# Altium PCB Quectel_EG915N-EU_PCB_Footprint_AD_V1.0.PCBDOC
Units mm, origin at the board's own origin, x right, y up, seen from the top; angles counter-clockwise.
Board outline 152.4 x 101.6 mm, 2 copper layers (Top Layer, Bottom Layer); 1 components, 0 nets, 126 pads, 0 vias.
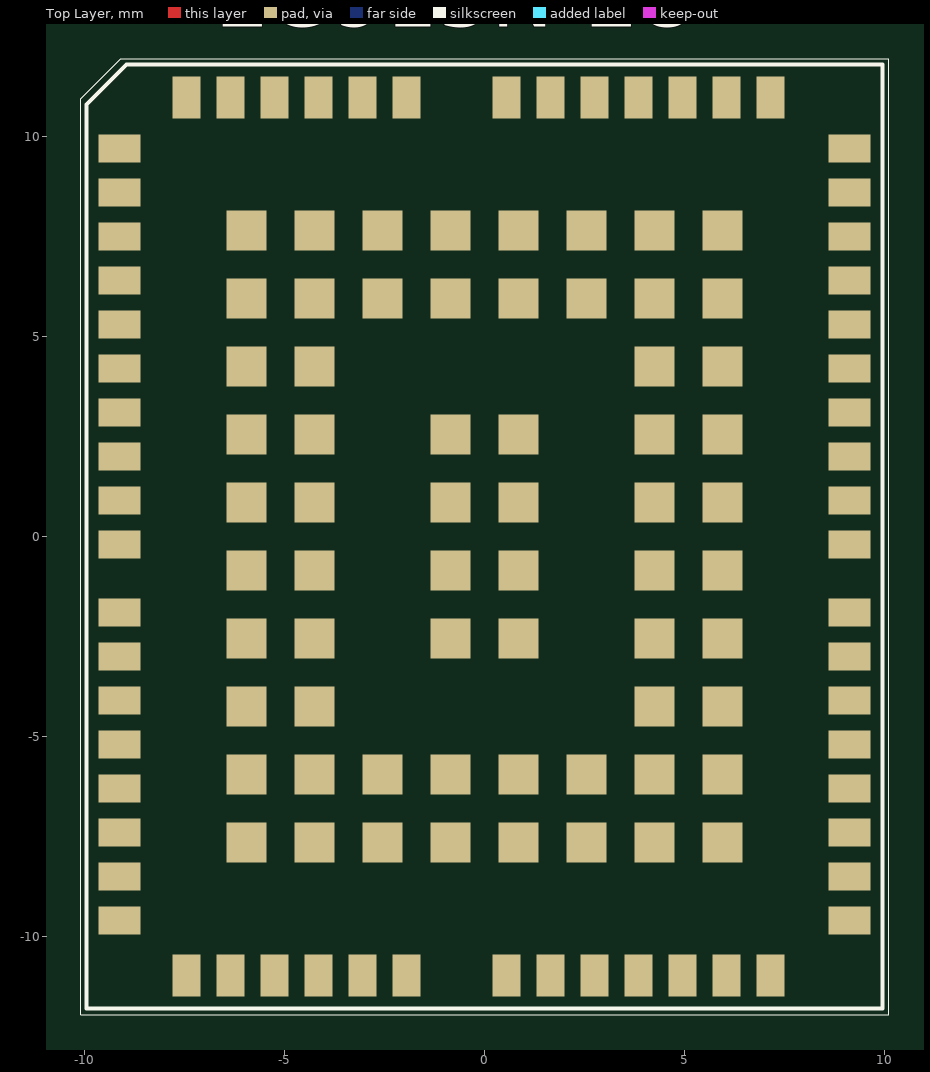
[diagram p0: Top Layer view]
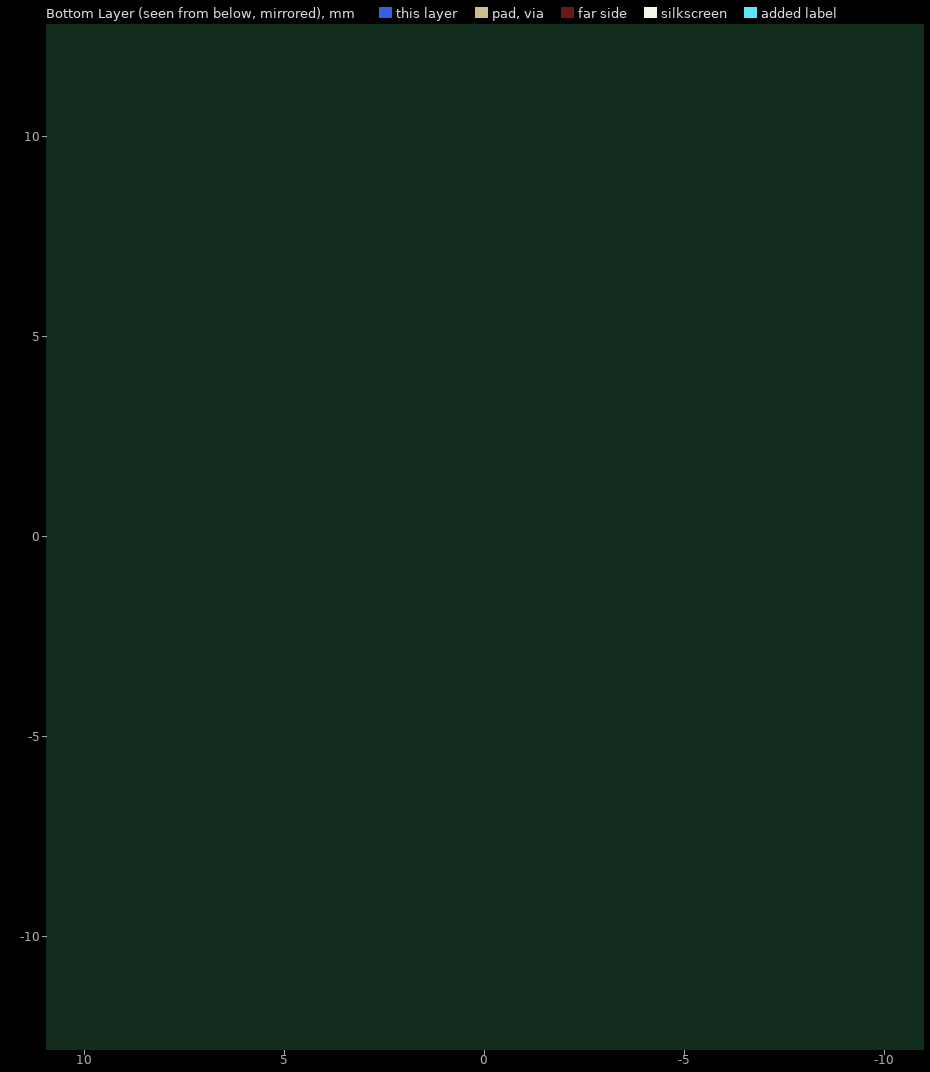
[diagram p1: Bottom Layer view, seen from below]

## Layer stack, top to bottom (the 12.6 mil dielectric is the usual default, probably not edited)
Top Layer: signal copper 0.0356
Dielectric: dielectric 0.32, FR-4, Dk 4.8
Bottom Layer: signal copper 0.0356

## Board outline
-50.546,-45.466 101.854,-45.466 101.854,56.134 -50.546,56.134

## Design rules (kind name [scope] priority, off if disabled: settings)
Clearance [All] p1: gap=0.254
FabricationTestPointUsage TestPointUsage [All] p1: valid=0 allowmultiple=FALSE
FabricationTestpoint Testpoint [(IsPad And (OnTopLayer Or OnBottomLayer))] p1: side=3 testpointundercomponent=TRUE minsize=1.016 maxsize=2.54 preferedsize=1.524 minholesize=0 maxholesize=1.016 preferedholesize=0.813 testpointgrid=0.025 allowsidetop=TRUE allowsidebottom=TRUE usegrid=TRUE gridtolerance=0
PolygonConnect [All] p1: connectstyle=Relief reliefconductorwidth=0.254 reliefentries=4 polygonreliefangle="90 Angle" airgapwidth=0.254
RoutingVias [All] p1: holewidth=0.711 width=1.27 viastyle="Through Hole" minholewidth=0.711 minwidth=1.27 maxholewidth=0.711 maxwidth=1.27
SolderMaskExpansion [All] p1: expansion=0.102
Width [All] p1: maxlimit=0.254 minlimit=0.254 preferedwidth=0.254
26 further rules are at their usual default settings.

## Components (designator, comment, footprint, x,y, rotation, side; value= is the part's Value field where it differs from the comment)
EG915N-EU "Comment" EG915N-EU 0,0 r0 top

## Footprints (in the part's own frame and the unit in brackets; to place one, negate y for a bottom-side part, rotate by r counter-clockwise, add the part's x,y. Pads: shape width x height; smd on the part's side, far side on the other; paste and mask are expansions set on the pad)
EG915N-EU [mm] "EG915U  Module LGA126Pin  19.9x23.6mm H2.4mm RO"
  rect 1.05x0.7 smd mask+0.05: 1(-9.125,9.7) 2(-9.125,8.6) 3(-9.125,7.5) 4(-9.125,6.4) 5(-9.125,5.3) 6(-9.125,4.2) 7(-9.125,3.1) 8(-9.125,2) 9(-9.125,0.9) 10(-9.125,-0.2) 11(-9.125,-1.9) 12(-9.125,-3) 13(-9.125,-4.1) 14(-9.125,-5.2) 15(-9.125,-6.3) 16(-9.125,-7.4) 17(-9.125,-8.5) 18(-9.125,-9.6) 32(9.125,-9.6) 33(9.125,-8.5) 34(9.125,-7.4) 35(9.125,-6.3) 36(9.125,-5.2) 37(9.125,-4.1) 38(9.125,-3) 39(9.125,-1.9) 40(9.125,-0.2) 41(9.125,0.9) 42(9.125,2) 43(9.125,3.1) 44(9.125,4.2) 45(9.125,5.3) 46(9.125,6.4) 47(9.125,7.5) 48(9.125,8.6) 49(9.125,9.7)
  rect 0.7x1.05 smd mask+0.05: 19(-7.45,-10.975) 20(-6.35,-10.975) 21(-5.25,-10.975) 22(-4.15,-10.975) 23(-3.05,-10.975) 24(-1.95,-10.975) 25(0.55,-10.975) 26(1.65,-10.975) 27(2.75,-10.975) 28(3.85,-10.975) 29(4.95,-10.975) 30(6.05,-10.975) 31(7.15,-10.975) 50(7.15,10.975) 51(6.05,10.975) 52(4.95,10.975) 53(3.85,10.975) 54(2.75,10.975) 55(1.65,10.975) 56(0.55,10.975) 57(-1.95,10.975) 58(-3.05,10.975) 59(-4.15,10.975) 60(-5.25,10.975) 61(-6.35,10.975) 62(-7.45,10.975)
  rect 1x1 smd mask+0.05: 63(-5.95,4.25) 64(-5.95,2.55) 65(-5.95,0.85) 66(-5.95,-0.85) 67(-5.95,-2.55) 68(-5.95,-4.25) 69(-2.55,-7.65) 70(-0.85,-7.65) 71(0.85,-7.65) 72(2.55,-7.65) 73(5.95,-4.25) 74(5.95,-2.55) 75(5.95,-0.85) 76(5.95,0.85) 77(5.95,2.55) 78(5.95,4.25) 79(2.55,7.65) 80(0.85,7.65) 81(-0.85,7.65) 82(-2.55,7.65) 83(-4.25,4.25) 84(-4.25,2.55) 85(-4.25,0.85) 86(-4.25,-0.85) 87(-4.25,-2.55) 88(-4.25,-4.25) 89(-2.55,-5.95) 90(-0.85,-5.95) 91(0.85,-5.95) 92(2.55,-5.95) 93(4.25,-4.25) 94(4.25,-2.55) 95(4.25,-0.85) 96(4.25,0.85) 97(4.25,2.55) 98(4.25,4.25) 99(2.55,5.95) 100(0.85,5.95) 101(-0.85,5.95) 102(-2.55,5.95) 103(-5.95,7.65) 104(-5.95,5.95) 105(-5.95,-5.95) 106(-5.95,-7.65) 107(-4.25,-7.65) 108(4.25,-7.65) 109(5.95,-7.65) 110(5.95,-5.95) 111(5.95,5.95) 112(5.95,7.65) 113(4.25,7.65) 114(-4.25,7.65) 115(-4.25,5.95) 116(-4.25,-5.95) 117(4.25,-5.95) 118(4.25,5.95) 119(-0.85,2.55) 120(-0.85,0.85) 121(-0.85,-0.85) 122(-0.85,-2.55) 123(0.85,-2.55) 124(0.85,-0.85) 125(0.85,0.85) 126(0.85,2.55)
  silkscreen extent -10.1,-11.95 10.1,11.95

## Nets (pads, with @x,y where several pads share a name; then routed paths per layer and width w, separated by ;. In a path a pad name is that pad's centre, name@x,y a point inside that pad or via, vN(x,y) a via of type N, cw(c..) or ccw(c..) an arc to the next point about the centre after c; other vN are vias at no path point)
pads on no net: EG915N-EU.1 EG915N-EU.2 EG915N-EU.3 EG915N-EU.4 EG915N-EU.5 EG915N-EU.6 EG915N-EU.7 EG915N-EU.8 EG915N-EU.9 EG915N-EU.10 EG915N-EU.11 EG915N-EU.12 EG915N-EU.13 EG915N-EU.14 EG915N-EU.15 EG915N-EU.16 EG915N-EU.17 EG915N-EU.18 EG915N-EU.19 EG915N-EU.20 EG915N-EU.21 EG915N-EU.22 EG915N-EU.23 EG915N-EU.24 EG915N-EU.25 EG915N-EU.26 EG915N-EU.27 EG915N-EU.28 EG915N-EU.29 EG915N-EU.30 EG915N-EU.31 EG915N-EU.32 EG915N-EU.33 EG915N-EU.34 EG915N-EU.35 EG915N-EU.36 EG915N-EU.37 EG915N-EU.38 EG915N-EU.39 EG915N-EU.40 EG915N-EU.41 EG915N-EU.42 EG915N-EU.43 EG915N-EU.44 EG915N-EU.45 EG915N-EU.46 EG915N-EU.47 EG915N-EU.48 EG915N-EU.49 EG915N-EU.50 EG915N-EU.51 EG915N-EU.52 EG915N-EU.53 EG915N-EU.54 EG915N-EU.55 EG915N-EU.56 EG915N-EU.57 EG915N-EU.58 EG915N-EU.59 EG915N-EU.60 EG915N-EU.61 EG915N-EU.62 EG915N-EU.63 EG915N-EU.64 EG915N-EU.65 EG915N-EU.66 EG915N-EU.67 EG915N-EU.68 EG915N-EU.69 EG915N-EU.70 EG915N-EU.71 EG915N-EU.72 EG915N-EU.73 EG915N-EU.74 EG915N-EU.75 EG915N-EU.76 EG915N-EU.77 EG915N-EU.78 EG915N-EU.79 EG915N-EU.80 EG915N-EU.81 EG915N-EU.82 EG915N-EU.83 EG915N-EU.84 EG915N-EU.85 EG915N-EU.86 EG915N-EU.87 EG915N-EU.88 EG915N-EU.89 EG915N-EU.90 EG915N-EU.91 EG915N-EU.92 EG915N-EU.93 EG915N-EU.94 EG915N-EU.95 EG915N-EU.96 EG915N-EU.97 EG915N-EU.98 EG915N-EU.99 EG915N-EU.100 EG915N-EU.101 EG915N-EU.102 EG915N-EU.103 EG915N-EU.104 EG915N-EU.105 EG915N-EU.106 EG915N-EU.107 EG915N-EU.108 EG915N-EU.109 EG915N-EU.110 EG915N-EU.111 EG915N-EU.112 EG915N-EU.113 EG915N-EU.114 EG915N-EU.115 EG915N-EU.116 EG915N-EU.117 EG915N-EU.118 EG915N-EU.119 EG915N-EU.120 EG915N-EU.121 EG915N-EU.122 EG915N-EU.123 EG915N-EU.124 EG915N-EU.125 EG915N-EU.126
